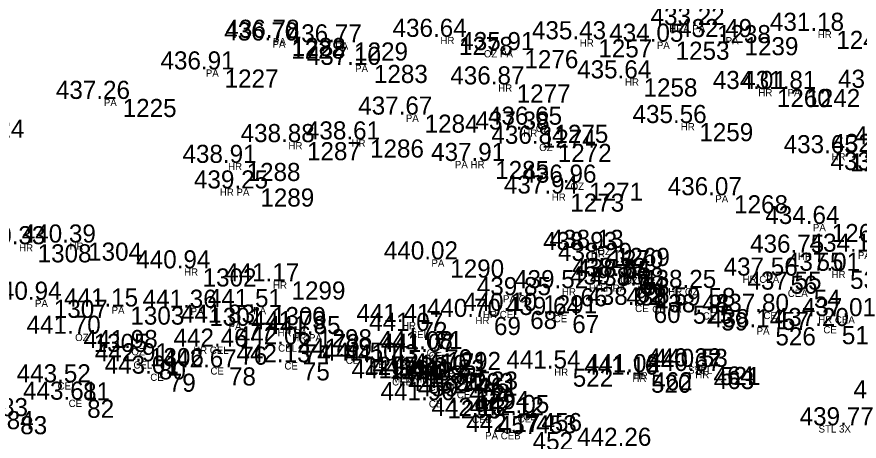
# Model space of a CAD drawing. Extents: x -639390 to -639075, y -1138747 to -1138358.
# Drawn here: x -639236.35 to -639201.49, y -1138641.7 to -1138624.12 of the extents above; entities that cross this region are included whole.
import ezdxf

# ---------------------------------------------------------------- set-up
doc = ezdxf.new("R2010")
doc.units = 0
for name, color, linetype in [('Vrstva 11', 7, 'Continuous'), ('Vrstva 12', 7, 'Continuous'), ('Vrstva 13', 7, 'Continuous'), ('Vrstva 57', 7, 'Continuous')]:
    doc.layers.add(name, color=color, linetype=linetype)

msp = doc.modelspace()

# ---------------------------------------------------------------- linework, layer by layer
at = {"layer": 'Vrstva 11'}
for p, q in [((-639207.65, -1138624.46), (-639207.65, -1138624.46)), ((-639202.71, -1138624.7), (-639202.71, -1138624.7)), ((-639225.27, -1138625.1), (-639225.27, -1138625.1)), ((-639225.25, -1138624.99), (-639225.25, -1138624.99)), ((-639222.67, -1138625.18), (-639222.67, -1138625.18)), ((-639218.33, -1138624.95), (-639218.33, -1138624.95)), ((-639212.56, -1138625.05), (-639212.56, -1138625.05)), ((-639209.36, -1138625.15), (-639209.36, -1138625.15)), ((-639206.51, -1138624.96), (-639206.51, -1138624.96)), ((-639215.62, -1138625.5), (-639215.62, -1138625.5)), ((-639221.85, -1138626.11), (-639221.85, -1138626.11)), ((-639228.03, -1138626.3), (-639228.03, -1138626.3)), ((-639215.94, -1138626.92), (-639215.94, -1138626.92)), ((-639210.69, -1138626.67), (-639210.69, -1138626.67)), ((-639205.17, -1138627.11), (-639205.17, -1138627.11)), ((-639203.95, -1138627.11), (-639203.95, -1138627.11)), ((-639232.25, -1138627.52), (-639232.25, -1138627.52)), ((-639219.75, -1138628.17), (-639219.75, -1138628.17)), ((-639214.38, -1138628.59), (-639214.38, -1138628.59)), ((-639208.38, -1138628.52), (-639208.38, -1138628.52)), ((-639214.9, -1138628.79), (-639214.9, -1138628.79)), ((-639224.62, -1138629.31), (-639224.62, -1138629.31)), ((-639222.01, -1138629.2), (-639222.01, -1138629.2)), ((-639214.24, -1138629.38), (-639214.24, -1138629.38)), ((-639216.83, -1138630.09), (-639216.83, -1138630.09)), ((-639202.14, -1138629.77), (-639202.14, -1138629.77)), ((-639227.12, -1138630.17), (-639227.12, -1138630.17)), ((-639212.94, -1138630.99), (-639212.94, -1138630.99)), ((-639226.55, -1138631.23), (-639226.55, -1138631.23)), ((-639213.72, -1138631.44), (-639213.72, -1138631.44)), ((-639206.94, -1138631.51), (-639206.94, -1138631.51)), ((-639202.9, -1138632.7), (-639202.9, -1138632.7)), ((-639235.77, -1138633.54), (-639235.77, -1138633.54)), ((-639233.68, -1138633.47), (-639233.68, -1138633.47)), ((-639212.1, -1138633.78), (-639212.1, -1138633.78)), ((-639211.83, -1138633.69), (-639211.83, -1138633.69)), ((-639203.53, -1138633.89), (-639203.53, -1138633.89)), ((-639218.69, -1138634.17), (-639218.69, -1138634.17)), ((-639211.48, -1138634.23), (-639211.48, -1138634.23)), ((-639228.94, -1138634.54), (-639228.94, -1138634.54)), ((-639210.89, -1138634.86), (-639210.89, -1138634.86)), ((-639210.72, -1138634.9), (-639210.72, -1138634.9)), ((-639204.61, -1138634.84), (-639204.61, -1138634.84)), ((-639202.14, -1138634.64), (-639202.14, -1138634.64)), ((-639225.26, -1138635.08), (-639225.26, -1138635.08)), ((-639210.97, -1138635.21), (-639210.97, -1138635.21)), ((-639210.17, -1138635.26), (-639210.17, -1138635.26)), ((-639214.84, -1138635.65), (-639214.84, -1138635.65)), ((-639213.3, -1138635.36), (-639213.3, -1138635.36)), ((-639208, -1138635.35), (-639208, -1138635.35)), ((-639203.64, -1138635.42), (-639203.64, -1138635.42)), ((-639235.1, -1138635.84), (-639235.1, -1138635.84)), ((-639231.93, -1138636.12), (-639231.93, -1138636.12)), ((-639228.66, -1138636.17), (-639228.66, -1138636.17)), ((-639226.07, -1138636.14), (-639226.07, -1138636.14)), ((-639215.38, -1138636.3), (-639215.38, -1138636.3)), ((-639210.27, -1138636.05), (-639210.27, -1138636.05)), ((-639208.65, -1138636.08), (-639208.65, -1138636.08)), ((-639207.47, -1138636.36), (-639207.47, -1138636.36)), ((-639204.96, -1138636.34), (-639204.96, -1138636.34)), ((-639216.88, -1138636.55), (-639216.88, -1138636.55)), ((-639213.64, -1138636.47), (-639213.64, -1138636.47)), ((-639227.09, -1138636.79), (-639227.09, -1138636.79)), ((-639224.16, -1138637.06), (-639224.16, -1138637.06)), ((-639219.92, -1138636.76), (-639219.92, -1138636.76)), ((-639205.23, -1138636.98), (-639205.23, -1138636.98)), ((-639202.48, -1138636.93), (-639202.48, -1138636.93)), ((-639233.45, -1138637.25), (-639233.45, -1138637.25)), ((-639223.55, -1138637.26), (-639223.55, -1138637.26)), ((-639219.3, -1138637.13), (-639219.3, -1138637.13)), ((-639224.76, -1138637.69), (-639224.76, -1138637.69)), ((-639231.12, -1138637.84), (-639231.12, -1138637.84)), ((-639227.38, -1138637.78), (-639227.38, -1138637.78)), ((-639218.9, -1138637.89), (-639218.9, -1138637.89)), ((-639218.82, -1138638), (-639218.82, -1138638)), ((-639230.75, -1138638.39), (-639230.75, -1138638.39)), ((-639224.79, -1138638.43), (-639224.79, -1138638.43)), ((-639222.25, -1138638.2), (-639222.25, -1138638.2)), ((-639221.2, -1138638.36), (-639221.2, -1138638.36)), ((-639220.33, -1138638.43), (-639220.33, -1138638.43)), ((-639227.85, -1138638.64), (-639227.85, -1138638.64)), ((-639217.56, -1138638.81), (-639217.56, -1138638.81)), ((-639213.62, -1138638.69), (-639213.62, -1138638.69)), ((-639207.79, -1138638.6), (-639207.79, -1138638.6)), ((-639207.78, -1138638.79), (-639207.78, -1138638.79)), ((-639207.52, -1138638.62), (-639207.52, -1138638.62)), ((-639230.34, -1138638.9), (-639230.34, -1138638.9)), ((-639220.03, -1138639.09), (-639220.03, -1138639.09)), ((-639219.14, -1138638.97), (-639219.14, -1138638.97)), ((-639218.3, -1138638.87), (-639218.3, -1138638.87)), ((-639217.58, -1138639.06), (-639217.58, -1138639.06)), ((-639210.38, -1138638.94), (-639210.38, -1138638.94)), ((-639210.33, -1138638.84), (-639210.33, -1138638.84)), ((-639233.89, -1138639.26), (-639233.89, -1138639.26)), ((-639217.91, -1138639.31), (-639217.91, -1138639.31)), ((-639217.65, -1138639.62), (-639217.65, -1138639.62)), ((-639233.72, -1138639.98), (-639233.72, -1138639.98)), ((-639218.81, -1138640), (-639218.81, -1138640)), ((-639214.91, -1138640.53), (-639214.91, -1138640.53)), ((-639216.72, -1138640.65), (-639216.72, -1138640.65)), ((-639215.13, -1138640.62), (-639215.13, -1138640.62)), ((-639215.28, -1138641.32), (-639215.28, -1138641.32))]:
    msp.add_line(p, q, dxfattribs=at)

# ---------------------------------------------------------------- texts
at = {"layer": 'Vrstva 12'}
for s, p in [('433.22 ', (-639210.119, -1138624.46)), ('431.18 ', (-639205.179, -1138624.7)), ('436.70 ', (-639227.769, -1138625.1)), ('436.78 ', (-639227.719, -1138624.99)), ('436.77 ', (-639225.139, -1138625.18)), ('436.64 ', (-639220.799, -1138624.95)), ('435.43 ', (-639215.029, -1138625.05)), ('434.05 ', (-639211.83, -1138625.15)), ('432.49 ', (-639208.979, -1138624.96)), ('435.91 ', (-639217.995, -1138625.5)), ('436.91 ', (-639230.405, -1138626.3)), ('437.10 ', (-639224.349, -1138626.11)), ('435.64 ', (-639213.159, -1138626.67)), ('436.87 ', (-639218.409, -1138626.92)), ('434.01 ', (-639207.545, -1138627.11)), ('431.81 ', (-639206.325, -1138627.11)), ('431.08 ', (-639202.359, -1138627.06)), ('437.26 ', (-639234.736, -1138627.52)), ('437.67 ', (-639222.219, -1138628.17)), ('436.65 ', (-639216.85, -1138628.59)), ('435.56 ', (-639210.866, -1138628.52)), ('437.38 ', (-639217.369, -1138628.79)), ('438.88 ', (-639227.089, -1138629.31)), ('438.61 ', (-639224.385, -1138629.2)), ('436.84 ', (-639216.709, -1138629.38)), ('431.29 ', (-639201.689, -1138629.4)), ('433.65 ', (-639204.61, -1138629.77)), ('432.09 ', (-639202.629, -1138629.72)), ('438.91 ', (-639229.495, -1138630.17)), ('437.91 ', (-639219.205, -1138630.09)), ('433.00 ', (-639202.669, -1138630.47)), ('436.96 ', (-639215.426, -1138630.99)), ('439.25 ', (-639229.02, -1138631.23)), ('437.94 ', (-639216.189, -1138631.44)), ('436.07 ', (-639209.409, -1138631.51)), ('434.64 ', (-639205.369, -1138632.7)), ('440.33 ', (-639238.239, -1138633.54)), ('440.39 ', (-639236.149, -1138633.47)), ('438.93 ', (-639214.569, -1138633.78)), ('438.13 ', (-639214.299, -1138633.69)), ('436.75 ', (-639206, -1138633.89)), ('434.10 ', (-639203.539, -1138633.85)), ('440.02 ', (-639221.159, -1138634.17)), ('438.29 ', (-639213.949, -1138634.23)), ('440.94 ', (-639231.409, -1138634.54)), ('437.01 ', (-639204.515, -1138634.64)), ('438.33 ', (-639213.359, -1138634.86)), ('438.34 ', (-639213.189, -1138634.9)), ('437.56 ', (-639207.096, -1138634.84)), ('441.17 ', (-639227.729, -1138635.08)), ('439.52 ', (-639215.769, -1138635.36)), ('439.16 ', (-639213.456, -1138635.21)), ('438.68 ', (-639212.639, -1138635.26)), ('438.25 ', (-639210.47, -1138635.35)), ('439.85 ', (-639217.31, -1138635.65)), ('437.55 ', (-639206.11, -1138635.42)), ('440.94 ', (-639237.569, -1138635.84)), ('438.92 ', (-639212.739, -1138636.05)), ('438.59 ', (-639211.119, -1138636.08)), ('441.15 ', (-639234.4, -1138636.12)), ('441.36 ', (-639231.146, -1138636.17)), ('441.51 ', (-639228.445, -1138636.14)), ('440.10 ', (-639217.879, -1138636.3)), ('438.48 ', (-639209.939, -1138636.36)), ('437.80 ', (-639207.459, -1138636.34)), ('441.83 ', (-639229.559, -1138636.79)), ('441.41 ', (-639222.295, -1138636.76)), ('440.70 ', (-639219.379, -1138636.55)), ('439.64 ', (-639216.109, -1138636.47)), ('437.01 ', (-639203.855, -1138636.52)), ('441.73 ', (-639226.629, -1138637.06)), ('441.07 ', (-639221.769, -1138637.13)), ('438.14 ', (-639207.699, -1138636.98)), ('437.20 ', (-639204.979, -1138636.93)), ('441.70 ', (-639235.949, -1138637.25)), ('441.85 ', (-639226.02, -1138637.26)), ('441.98 ', (-639233.589, -1138637.84)), ('442.46 ', (-639229.866, -1138637.78)), ('442.06 ', (-639227.246, -1138637.69)), ('441.08 ', (-639221.369, -1138637.89)), ('441.07 ', (-639221.289, -1138638)), ('442.91 ', (-639233.125, -1138638.39)), ('442.13 ', (-639227.259, -1138638.43)), ('441.69 ', (-639224.719, -1138638.2)), ('441.50 ', (-639223.699, -1138638.36)), ('441.43 ', (-639222.799, -1138638.43)), ('442.67 ', (-639230.319, -1138638.64)), ('441.50 ', (-639220.799, -1138638.87)), ('441.71 ', (-639219.935, -1138638.81)), ('441.54 ', (-639216.089, -1138638.69)), ('441.02 ', (-639212.799, -1138638.84)), ('440.32 ', (-639210.259, -1138638.6)), ('440.67 ', (-639210.249, -1138638.79)), ('440.53 ', (-639209.989, -1138638.62)), ('443.01 ', (-639232.715, -1138638.9)), ('441.84 ', (-639222.499, -1138639.09)), ('441.86 ', (-639221.626, -1138638.97)), ('441.83 ', (-639220.049, -1138639.06)), ('441.16 ', (-639212.866, -1138638.94)), ('443.52 ', (-639236.359, -1138639.26)), ('441.83 ', (-639220.379, -1138639.31)), ('441.90 ', (-639220.149, -1138639.62)), ('436.80 ', (-639201.719, -1138639.92)), ('443.61 ', (-639236.095, -1138639.98)), ('441.96 ', (-639221.296, -1138640)), ('442.12 ', (-639217.599, -1138640.62)), ('442.05 ', (-639217.38, -1138640.53)), ('443.83 ', (-639238.959, -1138640.66)), ('442.13 ', (-639219.189, -1138640.65)), ('442.17 ', (-639217.749, -1138641.32)), ('439.77 ', (-639203.949, -1138641.04)), ('442.26 ', (-639213.156, -1138641.89))]:
    msp.add_text(s, height=0.75, dxfattribs=at).set_placement(p)
at = {"layer": 'Vrstva 13'}
for s, p in [(' 1238', (-639207.65, -1138625.21)), (' 1241', (-639202.71, -1138625.45)), (' 1228', (-639225.27, -1138625.85)), (' 1282', (-639225.25, -1138625.74)), (' 1229', (-639222.67, -1138625.93)), (' 1278', (-639218.33, -1138625.7)), (' 1257', (-639212.56, -1138625.8)), (' 1253', (-639209.36, -1138625.9)), (' 1239', (-639206.51, -1138625.71)), (' 1276', (-639215.62, -1138626.25)), (' 1283', (-639221.85, -1138626.86)), (' 1227', (-639228.03, -1138627.05)), (' 1277', (-639215.94, -1138627.67)), (' 1258', (-639210.69, -1138627.42)), (' 1260', (-639205.17, -1138627.86)), (' 1242', (-639203.95, -1138627.86)), (' 1225', (-639232.25, -1138628.27)), (' 1284', (-639219.75, -1138628.92)), (' 1224', (-639238.55, -1138629.13)), (' 1275', (-639214.38, -1138629.34)), (' 1259', (-639208.38, -1138629.27)), (' 1274', (-639214.9, -1138629.54)), (' 1287', (-639224.62, -1138630.06)), (' 1286', (-639222.01, -1138629.95)), (' 1272', (-639214.24, -1138630.13)), (' 1285', (-639216.83, -1138630.84)), (' 1261', (-639202.14, -1138630.52)), (' 1288', (-639227.12, -1138630.92)), (' 1271', (-639212.94, -1138631.74)), (' 1289', (-639226.55, -1138631.98)), (' 1273', (-639213.72, -1138632.19)), (' 1268', (-639206.94, -1138632.26)), (' 1267', (-639202.9, -1138633.45)), (' 1308', (-639235.77, -1138634.29)), (' 1304', (-639233.68, -1138634.22)), (' 1270', (-639212.1, -1138634.53)), (' 1269', (-639211.83, -1138634.44)), (' 55', (-639203.53, -1138634.64)), (' 1290', (-639218.69, -1138634.92)), (' 65', (-639211.48, -1138634.98)), (' 1302', (-639228.94, -1138635.29)), (' 53', (-639202.14, -1138635.39)), (' 64', (-639210.89, -1138635.61)), (' 63', (-639210.72, -1138635.65)), (' 56', (-639204.61, -1138635.59)), (' 1299', (-639225.26, -1138635.83)), (' 62', (-639210.97, -1138635.96)), (' 61', (-639210.17, -1138636.01)), (' 1291', (-639214.84, -1138636.4)), (' 66', (-639213.3, -1138636.11)), (' 58', (-639208, -1138636.1)), (' 54', (-639203.64, -1138636.17)), (' 1307', (-639235.1, -1138636.59)), (' 1303', (-639231.93, -1138636.87)), (' 1301', (-639228.66, -1138636.92)), (' 1300', (-639226.07, -1138636.89)), (' 68', (-639215.38, -1138637.05)), (' 60', (-639210.27, -1138636.8)), (' 525', (-639208.65, -1138636.83)), (' 59', (-639207.47, -1138637.11)), (' 57', (-639204.96, -1138637.09)), (' 69', (-639216.88, -1138637.3)), (' 67', (-639213.64, -1138637.22)), (' 77', (-639227.09, -1138637.54)), (' 1298', (-639224.16, -1138637.81)), (' 72', (-639219.92, -1138637.51)), (' 526', (-639205.23, -1138637.73)), (' 51', (-639202.48, -1138637.68)), (' 1305', (-639233.45, -1138638)), (' 73', (-639223.55, -1138638.01)), (' 71', (-639219.3, -1138637.88)), (' 76', (-639227.38, -1138638.53)), (' 74', (-639224.76, -1138638.44)), (' 1306', (-639231.12, -1138638.59)), (' 70', (-639218.9, -1138638.64)), (' 1292', (-639218.82, -1138638.75)), (' 80', (-639230.75, -1138639.14)), (' 75', (-639224.79, -1138639.18)), (' 1297', (-639222.25, -1138638.95)), (' 1296', (-639221.2, -1138639.11)), (' 460', (-639220.33, -1138639.18)), (' 78', (-639227.85, -1138639.39)), (' 523', (-639217.56, -1138639.56)), (' 522', (-639213.62, -1138639.44)), (' 464', (-639207.79, -1138639.35)), (' 463', (-639207.78, -1138639.54)), (' 521', (-639207.52, -1138639.37)), (' 79', (-639230.34, -1138639.65)), (' 459', (-639220.03, -1138639.84)), (' 524', (-639219.14, -1138639.72)), (' 1293', (-639218.3, -1138639.62)), (' 461', (-639217.58, -1138639.81)), (' 520', (-639210.38, -1138639.69)), (' 462', (-639210.33, -1138639.59)), (' 81', (-639233.89, -1138640.01)), (' 458', (-639217.91, -1138640.06)), (' 1294', (-639217.65, -1138640.37)), (' 82', (-639233.72, -1138640.73)), (' 1295', (-639218.81, -1138640.75)), (' 84', (-639237.05, -1138641.2)), (' 456', (-639214.91, -1138641.28)), (' 83', (-639236.49, -1138641.41)), (' 457', (-639216.72, -1138641.4)), (' 453', (-639215.13, -1138641.37)), (' 452', (-639215.28, -1138642.07))]:
    msp.add_text(s, height=0.75, dxfattribs=at).set_placement(p)
at = {"layer": 'Vrstva 57'}
for s, p in [('HRA PA', (-639209.35, -1138624.76)), ('HR', (-639203.199, -1138625)), ('PA', (-639225.77, -1138625.4)), ('PA', (-639225.75, -1138625.29)), ('PA', (-639223.17, -1138625.48)), ('HR', (-639218.819, -1138625.25)), ('HR', (-639213.049, -1138625.35)), ('PA', (-639209.86, -1138625.45)), ('PA', (-639207.01, -1138625.26)), ('OZ PA', (-639217.02, -1138625.8)), ('PA', (-639222.35, -1138626.41)), ('PA', (-639228.53, -1138626.6)), ('HR', (-639216.429, -1138627.22)), ('HR', (-639211.179, -1138626.97)), ('HR', (-639205.659, -1138627.41)), ('PA', (-639204.45, -1138627.41)), ('PA', (-639232.75, -1138627.82)), ('PA', (-639220.25, -1138628.47)), ('OZ', (-639214.869, -1138628.89)), ('HR', (-639208.869, -1138628.82)), ('HR', (-639215.389, -1138629.09)), ('HR', (-639225.109, -1138629.61)), ('HR', (-639222.499, -1138629.5)), ('OZ', (-639214.729, -1138629.68)), ('PA HR', (-639218.219, -1138630.39)), ('HR', (-639202.629, -1138630.07)), ('HR', (-639227.609, -1138630.47)), ('OZ', (-639213.429, -1138631.29)), ('HR PA', (-639227.95, -1138631.53)), ('HR', (-639214.209, -1138631.74)), ('PA', (-639207.44, -1138631.81)), ('PA', (-639203.4, -1138633)), ('HR', (-639236.259, -1138633.84)), ('HR', (-639234.169, -1138633.77)), ('HR', (-639212.589, -1138634.08)), ('OZ', (-639212.319, -1138633.99)), ('HR', (-639204.019, -1138634.19)), ('PA', (-639201.54, -1138634.15)), ('PA', (-639219.19, -1138634.47)), ('OZ', (-639211.969, -1138634.53)), ('HR', (-639229.429, -1138634.84)), ('OZ', (-639211.379, -1138635.16)), ('OZ', (-639211.209, -1138635.2)), ('HR CEA', (-639206.31, -1138635.14)), ('HR', (-639202.629, -1138634.94)), ('HR', (-639225.749, -1138635.38)), ('HR HRA', (-639212.67, -1138635.51)), ('HR', (-639210.659, -1138635.56)), ('PA CE', (-639216.228, -1138635.95)), ('HR', (-639213.789, -1138635.66)), ('HR OZ', (-639209.389, -1138635.65)), ('CEA', (-639204.44, -1138635.72)), ('PA', (-639235.6, -1138636.14)), ('PA', (-639232.43, -1138636.42)), ('PA', (-639229.16, -1138636.47)), ('PA', (-639226.57, -1138636.44)), ('HR CEL', (-639217.055, -1138636.6)), ('CE', (-639210.758, -1138636.35)), ('CE PA', (-639210.05, -1138636.38)), ('CE', (-639207.958, -1138636.66)), ('CE', (-639205.448, -1138636.64)), ('HR', (-639217.369, -1138636.85)), ('CE', (-639214.128, -1138636.77)), ('HR CEA', (-639203.18, -1138636.82)), ('PA', (-639227.59, -1138637.09)), ('HR PA', (-639225.56, -1138637.36)), ('HR', (-639220.409, -1138637.06)), ('PA', (-639205.73, -1138637.28)), ('CE', (-639202.968, -1138637.23)), ('OZ', (-639233.939, -1138637.55)), ('HR PA', (-639224.95, -1138637.56)), ('CEL', (-639220.075, -1138637.43)), ('HR CEL', (-639229.055, -1138638.08)), ('CEL', (-639225.535, -1138637.99)), ('OZ', (-639231.609, -1138638.14)), ('CE', (-639219.388, -1138638.19)), ('CE', (-639219.307, -1138638.3)), ('CEL', (-639231.525, -1138638.69)), ('CE', (-639225.277, -1138638.73)), ('CE', (-639222.738, -1138638.5)), ('CE', (-639221.688, -1138638.66)), ('CE', (-639220.818, -1138638.73)), ('CE', (-639228.338, -1138638.94)), ('HR', (-639218.049, -1138639.11)), ('HR', (-639214.109, -1138638.99)), ('STL', (-639208.565, -1138638.9)), ('STL', (-639208.295, -1138638.92)), ('HR', (-639208.269, -1138639.09)), ('CE', (-639230.828, -1138639.2)), ('CEB', (-639220.819, -1138639.39)), ('MEZNIK', (-639220.815, -1138639.27)), ('CE', (-639218.787, -1138639.17)), ('HR', (-639218.069, -1138639.36)), ('HR', (-639210.869, -1138639.24)), ('HR', (-639210.819, -1138639.14)), ('CEL', (-639234.665, -1138639.56)), ('CE HR', (-639219.299, -1138639.61)), ('CE', (-639218.138, -1138639.92)), ('CE', (-639234.208, -1138640.28)), ('CE', (-639219.297, -1138640.3)), ('CE', (-639215.397, -1138640.83)), ('CEB', (-639217.509, -1138640.95)), ('CE', (-639215.618, -1138640.92)), ('STL 3X', (-639203.167, -1138641.34)), ('PA CEB', (-639216.969, -1138641.62))]:
    msp.add_text(s, height=0.3, dxfattribs=at).set_placement(p)

doc.saveas('drawing.dxf')
